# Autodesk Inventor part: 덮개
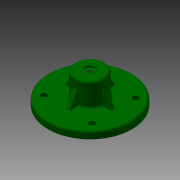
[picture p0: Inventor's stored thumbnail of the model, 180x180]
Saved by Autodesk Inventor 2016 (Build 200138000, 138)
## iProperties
Created: 2017-08
Part Number: 덮개
Material: 알루미늄 6061
Document SubType Name: Modeling
Designer: mduedu
Density: 2.71 g/cm^3
Mass: 358.12 g
Surface Area: 294.002 cm^2
Volume: 132.148 cm^3
Appearance: 알루미늄 - 평지
Author: mduedu
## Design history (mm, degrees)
sketch "스케치1"
  geometry: C1 r 57.5 at (0, 0); 1 further point
  constraints: 1 centre point, 1 coincident
  dimensions: "d69" = 115 diameter of C1
extrude "돌출1" new body sketch "스케치1" distance "d5" = 10; taper "d6" = 0 deg
sketch "스케치2"
  geometry: C1 r 20 at (0, 0); 1 further point
  constraints: 1 centre point, 1 coincident
  dimensions: "d55" = 40 diameter of C1
extrude "돌출2" join sketch "스케치2" distance "d9" = 32; taper "d10" = 0 deg
sketch "스케치3"
  geometry: L1 (-26, -26)-(26, -26); L2 (26, -26)-(26, 26); L3 (26, 26)-(-26, 26); L4 (-26, 26)-(-26, -26); L5 (-26, -26)-(26, 26); L6 (26, -26)-(-26, 26); 1 further point
  constraints: 12 end point, 2 midpoint, 2 parallel, 2 perpendicular, 1 horizontal
  dimensions: "d11" = 52 distance of L3.end L2.end
extrude "돌출3" join sketch "스케치3" distance "d12" = 6; taper "d13" = 0 deg
sketch "스케치4"
  geometry: L1 (-17, -17)-(17, -17); L2 (17, -17)-(17, 17); L3 (17, 17)-(-17, 17); L4 (-17, 17)-(-17, -17); L5 (-17, -17)-(17, 17); L6 (17, -17)-(-17, 17); 1 further point
  constraints: 12 end point, 2 midpoint, 2 parallel, 2 perpendicular, 1 horizontal
  dimensions: "d14" = 34 distance of L2.end L3.end
extrude "돌출4" cut sketch "스케치4" distance "d16" = 5; taper "d17" = 0 deg
sketch "스케치5"
  geometry: C1 r 9 at (0, 0); 1 further point
  constraints: 1 centre point, 1 coincident
  dimensions: "d18" = 18 diameter of C1
extrude "돌출5" cut sketch "스케치5" distance "d19" = 34; taper "d20" = 0 deg
sketch "스케치6"
  geometry: 2 further points
  constraints: 1 coincident
hole "구멍1" sketch "스케치6" at (0, 0) diameter "d21" = 5.917; stored, may be unused: countersink angle "d25" = 90 deg, drill point angle "d27" = 118 deg; dims "d22" = 6, "d23" = 14, "d24" = 2, "d26" = 8
fillet "모깎기3" dims "d38" = 3
fillet "모깎기4" dims "d39" = 3
fillet "모깎기5" dims "d40" = 3
chamfer "모따기2" distance "d70" = 6; stored, may be unused: second distance "d71" = 2, angle "d72" = 45 deg
chamfer "모따기1" distance "d41" = 1; stored, may be unused: second distance "d42" = 2, angle "d43" = 45 deg
fillet "모깎기6" dims "d44" = 3
fillet "모깎기7" dims "d45" = 3
fillet "모깎기8" dims "d46" = 3
sketch "스케치9"
  geometry: L1 (-33, -30)-(33, -30); L2 (33, -30)-(33, 30); L3 (33, 30)-(-33, 30); L4 (-33, 30)-(-33, -30); L5 (-33, -30)-(33, 30); L6 (33, -30)-(-33, 30); C1 r 54.5 at (0, 0) reference; 3 further points
  constraints: 12 end point, 2 coincident, 2 midpoint, 2 parallel, 2 point on line, 1 horizontal, 1 perpendicular
  dimensions: "d77" = 66 distance of L2.end L3.end; "d79" = 60 distance of L1.end L2.end
hole "구멍3" sketch "스케치9" at (-33, -30), (-33, 30), (33, 30), (33, -30) diameter "d48" = 4.5; stored, may be unused: countersink angle "d52" = 90 deg, drill point angle "d54" = 0 deg; dims "d49" = 6, "d50" = 8, "d51" = 4.6, "d53" = 8
sketch "스케치10"
  geometry: L1 (-7, 40)-(-2.958, 40) reference; L2 (-2.958, 40)-(-2.958, 33) reference; L3 (-2.958, 33)-(-6, 33) reference; L4 (-9, 30)-(-9, -1) reference; L5 (-9, -1)-(-14, -1) reference; L6 (-17, -4)-(-17, -6) reference; L7 (-17, -6)-(-25, -6) reference; L8 (-25, -6)-(-26, -5) reference; L9 (-26, -5)-(-26, 0) reference; L10 (-26, 0)-(-57.5, 0) reference; L11 (-54.5, 10)-(-23, 10) reference; L12 (-20, 13)-(-20, 39) reference; L13 (-17, 42)-(-7, 42) reference; L14 (-7, 42)-(-7, 40) reference; L15 (2.958, 40)-(7, 40) reference; L16 (7, 40)-(7, 42) reference; L17 (7, 42)-(17, 42) reference; L18 (20, 39)-(20, 13) reference; L19 (23, 10)-(54.5, 10) reference; L20 (57.5, 0)-(26, 0) reference; L21 (26, 0)-(26, -5) reference; L22 (26, -5)-(25, -6) reference; L23 (25, -6)-(17, -6) reference; L24 (17, -6)-(17, -4) reference; L25 (14, -1)-(9, -1) reference; L26 (9, -1)-(9, 30) reference; L27 (6, 33)-(2.958, 33) reference; L28 (2.958, 33)-(2.958, 40) reference; L29 (31.547, 10)-(20, 30); L30 (-57.5, 0)-(-57.5, 7) reference; L31 (57.5, 7)-(57.5, 0) reference; A1 r 3 centre (-6, 30) between (-6, 33) and (-9, 30) reference; A2 r 3 centre (-14, -4) between (-14, -1) and (-17, -4) reference; A3 r 3 centre (-23, 13) between (-23, 10) and (-20, 13) reference; A4 r 3 centre (-17, 39) between (-17, 42) and (-20, 39) reference; A5 r 3 centre (17, 39) between (20, 39) and (17, 42) reference; A6 r 3 centre (23, 13) between (20, 13) and (23, 10) reference; A7 r 3 centre (14, -4) between (17, -4) and (14, -1) reference; A8 r 3 centre (6, 30) between (9, 30) and (6, 33) reference; A9 r 3 centre (-54.5, 7) between (-54.5, 10) and (-57.5, 7) reference; 2 further points
  constraints: 2 end point, 2 point on line, 1 other
  dimensions: "d56" = 20 distance from line of L29.end L19; "d57" = 120 deg angle of L29 L19
feature "리브1" sketch "스케치10" dims "d58" = 1, "d59" = 6, "d60" = 0, "d61" = 0, "d62" = 1, "d63" = 1
fillet "모깎기9" dims "d64" = 1
fillet "모깎기10" dims "d65" = 1
node "솔리드1"
pattern_circular "원형 패턴1" dims "d67" = 360 deg
node "절단 모서리 투영1"
